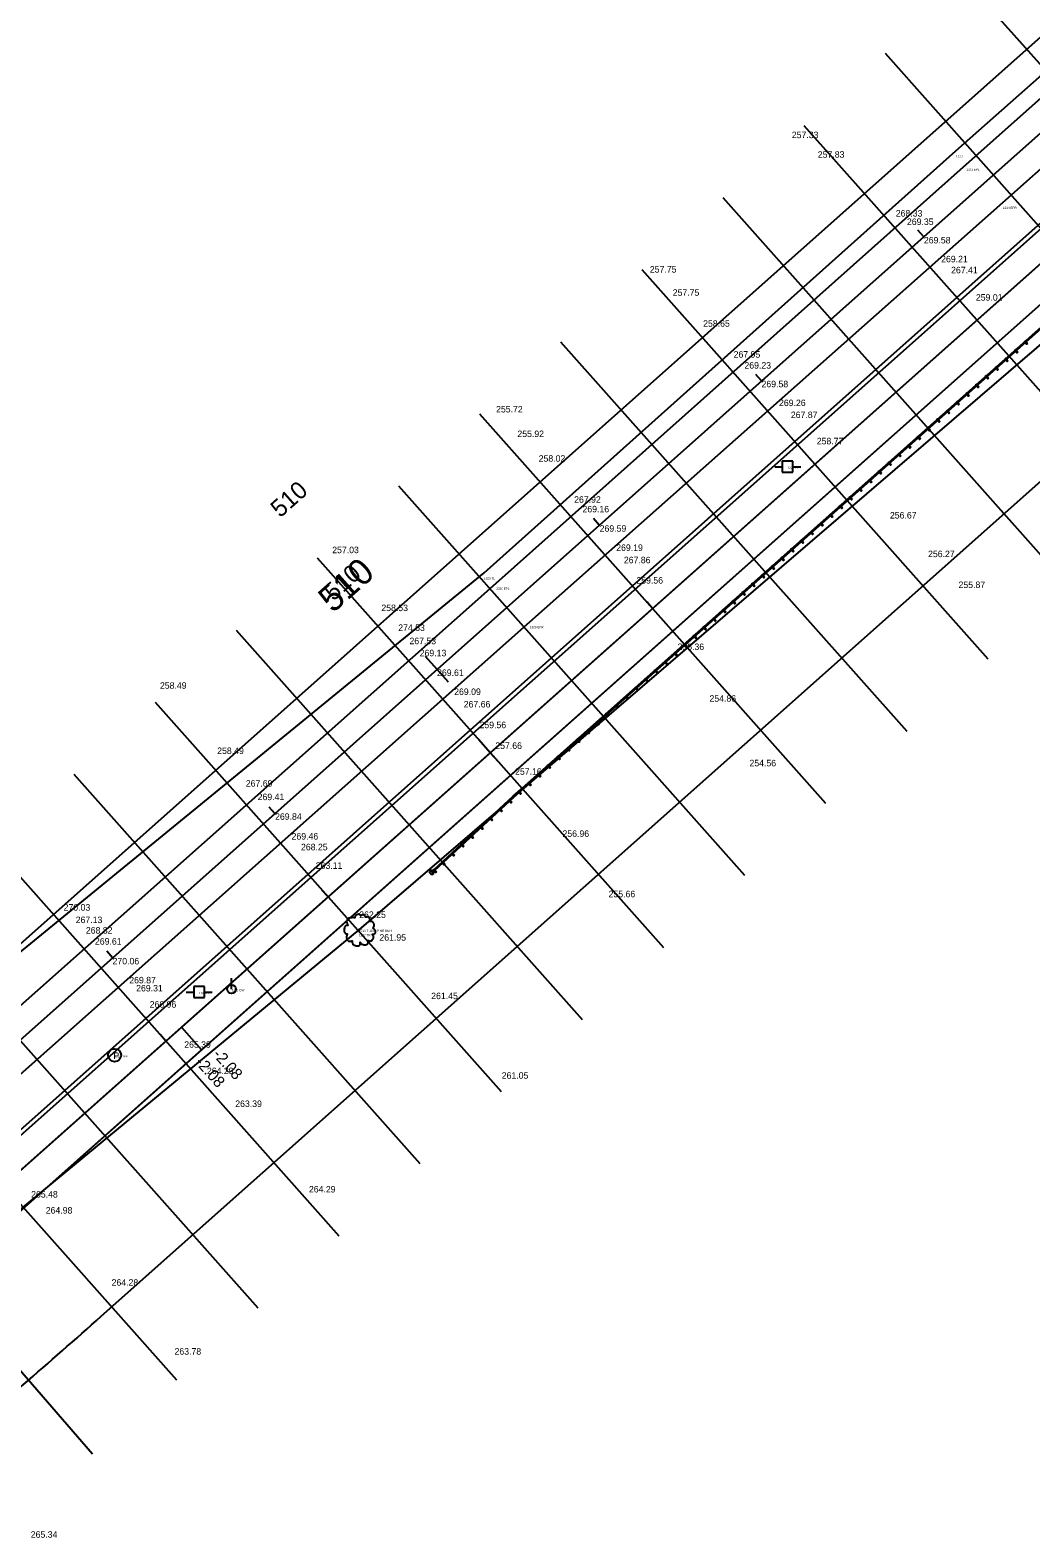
# Model space of a CAD drawing. Extents: x 49683 to 58852, y 49525 to 54803.
# Drawn here: x 52731 to 53192, y 50615 to 51310 of the extents above; entities that cross this region are included whole.
import ezdxf

# ---------------------------------------------------------------- set-up
doc = ezdxf.new("R2010")
doc.units = 0
for name, color, linetype in [('Level 1', 7, 'Continuous'), ('Level 11', 7, 'Continuous'), ('Level 13', 7, 'Continuous'), ('Level 19', 7, 'Continuous'), ('Level 20', 7, 'Continuous'), ('Level 21', 7, 'Continuous'), ('Level 27', 7, 'Continuous'), ('Level 29', 7, 'Continuous'), ('Level 3', 7, 'Continuous'), ('Level 32', 7, 'Continuous'), ('Level 33', 7, 'Continuous'), ('Level 50', 7, 'Continuous'), ('Level 53', 7, 'Continuous'), ('Level 59', 7, 'Continuous'), ('Level 61', 7, 'Continuous'), ('Level 63', 7, 'Continuous'), ('Level 9', 7, 'Continuous')]:
    doc.layers.add(name, color=color, linetype=linetype)

# ---------------------------------------------------------------- blocks, each defined once
blk = doc.blocks.new('TPP')
at = {"layer": 'Level 9'}
blk.add_circle((0, 0), 3, dxfattribs=at)
blk.add_text('P', height=3, dxfattribs=at).set_placement((-0.59, -1.73))
blk = doc.blocks.new('PP')
at = {"layer": 'Level 9'}
for p, q in [((2.53, 2.45), (-2.47, 2.45)), ((-2.47, 2.45), (-2.47, -2.55)), ((2.53, -2.55), (2.53, 2.45)), ((-5.91, -0.11), (-2.44, -0.11)), ((-2.47, -2.55), (2.53, -2.55)), ((2.45, -0.11), (6.09, -0.11))]:
    blk.add_line(p, q, dxfattribs=at)
blk = doc.blocks.new('GW')
at = {"layer": 'Level 9'}
blk.add_line((0, 0), (0, 5), dxfattribs=at)
blk.add_circle((0, 0), 2, dxfattribs=at)
blk = doc.blocks.new('T1')
at = {"layer": 'Level 11'}
for centre, radius in [((0, 0), 0.25), ((-0.01, -0.02), 0.0001)]:
    blk.add_circle(centre, radius, dxfattribs=at)
for points in [[(0.13, 7.17), (-0.17, 7.19), (-0.49, 7.09), (-0.74, 6.99), (-0.97, 6.92), (-1.19, 6.82), (-1.49, 6.64), (-1.72, 6.44), (-1.84, 6.19), (-1.89, 5.97), (-1.94, 5.69), (-1.94, 5.52), (-2.07, 5.49), (-2.22, 5.52), (-2.47, 5.59), (-2.72, 5.59), (-2.97, 5.59), (-3.32, 5.57), (-3.67, 5.57), (-3.94, 5.52), (-4.27, 5.47), (-4.64, 5.34), (-4.99, 5.22), (-5.29, 4.97), (-5.54, 4.49), (-5.67, 4.14), (-5.82, 3.89), (-5.67, 3.44), (-5.49, 3.09), (-5.47, 2.89), (-5.39, 2.47), (-5.29, 2.24), (-5.17, 2.04), (-5.24, 2.02), (-5.62, 1.97), (-5.92, 1.87), (-6.34, 1.64), (-6.57, 1.42), (-6.67, 1.09), (-6.69, 0.75), (-6.79, 0.55), (-6.87, 0.27), (-6.89, 0.2), (-6.94, -0.13), (-6.84, -0.58), (-6.82, -0.93), (-6.69, -1.15), (-6.54, -1.33), (-6.37, -1.58), (-5.97, -1.8), (-5.64, -1.9), (-5.44, -1.93), (-5.62, -2.43), (-5.67, -2.78), (-5.79, -3.18), (-5.79, -3.25), (-5.84, -3.73), (-5.69, -4.05), (-5.62, -4.43), (-5.44, -4.65), (-5.17, -4.95), (-4.84, -5.18), (-4.34, -5.3), (-3.94, -5.28), (-3.37, -5.1), (-3.12, -5.03), (-3.14, -5.2), (-3.12, -5.58), (-3.12, -6), (-2.97, -6.33), (-2.87, -6.6), (-2.72, -6.85), (-2.39, -7.08), (-1.99, -7.15), (-1.57, -7.3), (-1.12, -7.38), (-0.62, -7.4), (-0.02, -7.25), (0.26, -7.13), (0.36, -6.95), (0.56, -6.58), (0.51, -6.35), (0.53, -5.75), (0.63, -5.93), (0.81, -6.28), (1.31, -6.58), (1.71, -6.75), (2.18, -6.9), (2.48, -6.98), (2.96, -6.9), (3.33, -6.83), (3.71, -6.7), (4.01, -6.43), (4.18, -6.15), (4.23, -5.88), (4.31, -5.5), (4.36, -5.33)], [(4.36, -5.33), (4.28, -5.15), (4.23, -4.9), (4.31, -4.93), (4.48, -4.98), (4.75, -5.1), (4.98, -5.18), (5.3, -5.15), (5.58, -5.05), (6.03, -4.78), (6.3, -4.3), (6.58, -3.9), (6.65, -3.58), (6.6, -3.35), (6.58, -2.85), (6.38, -2.6), (6.33, -2.48), (6.23, -2.08), (6.3, -2.03), (6.58, -1.98), (6.95, -1.85), (7.23, -1.73), (7.45, -1.55), (7.53, -1.33), (7.5, -0.93), (7.55, -0.53), (7.48, -0.38), (7.38, -0.23), (7.3, -0.03), (7.15, 0.12), (7.05, 0.27), (6.95, 0.37), (6.83, 0.52), (6.65, 0.65), (6.5, 0.7), (6.45, 0.85), (6.6, 1.04), (6.65, 1.14), (6.68, 1.37), (6.9, 1.72), (6.95, 2.12), (6.9, 2.54), (6.85, 2.82), (6.7, 3.09), (6.5, 3.34), (6.38, 3.52), (6.2, 3.64), (5.88, 3.77), (5.63, 3.82), (5.28, 3.82), (5.08, 3.87), (5.1, 3.92), (5.1, 4.07), (5.1, 4.34), (5.03, 4.79), (4.88, 5.29), (4.88, 5.32), (4.78, 5.57), (4.56, 5.77), (4.38, 5.87), (4.18, 5.99), (3.93, 6.02), (3.63, 6.02), (3.36, 5.97), (3.16, 5.87), (2.98, 5.74), (2.91, 5.89), (2.81, 6.19), (2.76, 6.34), (2.61, 6.52), (2.38, 6.72), (1.93, 6.84), (1.31, 6.77), (1.01, 6.57), (0.86, 6.39), (0.81, 6.52), (0.61, 6.72), (0.51, 6.89), (0.33, 7.02), (0.18, 7.12), (0.08, 7.17)]]:
    blk.add_spline(points, degree=3, dxfattribs=at)

msp = doc.modelspace()

# ---------------------------------------------------------------- linework, layer by layer
at = {"layer": 'Level 1'}
for p, q in [((52544.81, 50683.3), (55534.58, 53340.86)), ((53142.87, 51214.91), (53140.21, 51217.9)), ((53068.13, 51148.47), (53065.47, 51151.46)), ((52993.38, 51082.03), (52990.73, 51085.02)), ((52918.64, 51015.6), (52913.33, 51021.58)), ((52923.96, 51009.62), (52918.64, 51015.6)), ((52843.9, 50949.16), (52841.24, 50952.15)), ((52769.16, 50882.73), (52766.5, 50885.72))]:
    msp.add_line(p, q, dxfattribs=at)
at = {"layer": 'Level 11'}
for p, q in [((53157.7, 51254.45), (53424.49, 51490.93)), ((52940.3, 51059.99), (53157.7, 51254.45)), ((52882.73, 50895.61), (53245.86, 51207.55)), ((52688.43, 50854.08), (52940.3, 51059.99)), ((52579.25, 50645.17), (52882.73, 50895.61))]:
    msp.add_line(p, q, dxfattribs=at)
at = {"layer": 'Level 13'}
for p, q in [((52637.37, 50809.73), (53363.85, 51455.49)), ((53407.7, 51406.16), (52566.74, 50658.64))]:
    msp.add_line(p, q, dxfattribs=at)
at = {"layer": 'Level 19'}
for p, q in [((52714.15, 50773.62), (54181.77, 52078.16)), ((53167.42, 51176.52), (53164.76, 51179.51)), ((53092.67, 51110.08), (53090.02, 51113.07)), ((53017.93, 51043.65), (53015.28, 51046.64)), ((52943.19, 50977.21), (52937.88, 50983.19)), ((52943.19, 50977.21), (52948.51, 50971.23)), ((52868.45, 50910.77), (52865.79, 50913.76)), ((52793.71, 50844.34), (52791.05, 50847.33))]:
    msp.add_line(p, q, dxfattribs=at)
at = {"layer": 'Level 20'}
for p, q in [((52704.85, 50784.08), (53476.26, 51469.77)), ((52723.45, 50763.15), (53495.78, 51449.66))]:
    msp.add_line(p, q, dxfattribs=at)
at = {"layer": 'Level 27'}
for p, q in [((52953.7, 50957.11), (53467.54, 51413.86)), ((52954.03, 50956.74), (53467.88, 51413.49)), ((52953.7, 50957.11), (52916.99, 50923.15)), ((52953.7, 50957.11), (52958.33, 50961.23)), ((52954.04, 50956.75), (52917.33, 50922.78)), ((52915.74, 50923.07), (52914.98, 50922.42)), ((52914.98, 50922.42), (52916.28, 50920.9)), ((52915.74, 50923.07), (52916.99, 50923.15)), ((52915.74, 50923.07), (52917.04, 50921.55)), ((52916.99, 50923.15), (52917.32, 50922.77)), ((52917.32, 50922.77), (52917.04, 50921.55)), ((52917.04, 50921.55), (52916.28, 50920.9))]:
    msp.add_line(p, q, dxfattribs=at)
for points in [[(53190.66, 51165.73), (53190.28, 51165.41), (53189.31, 51166.56), (53189.7, 51166.88)], [(53181.69, 51157.76), (53181.31, 51157.44), (53180.35, 51158.59), (53180.73, 51158.91)], [(53186.18, 51161.74), (53185.79, 51161.42), (53184.83, 51162.57), (53185.21, 51162.89)], [(53177.21, 51153.77), (53176.82, 51153.45), (53175.86, 51154.6), (53176.24, 51154.92)], [(53168.24, 51145.8), (53167.85, 51145.48), (53166.89, 51146.63), (53167.28, 51146.95)], [(53172.72, 51149.78), (53172.34, 51149.46), (53171.38, 51150.62), (53171.76, 51150.94)], [(53159.27, 51137.83), (53158.88, 51137.51), (53157.92, 51138.66), (53158.31, 51138.98)], [(53163.75, 51141.81), (53163.37, 51141.49), (53162.41, 51142.64), (53162.79, 51142.96)], [(53150.3, 51129.85), (53149.92, 51129.53), (53148.95, 51130.68), (53149.34, 51131)], [(53154.78, 51133.84), (53154.4, 51133.52), (53153.44, 51134.67), (53153.82, 51134.99)], [(53145.82, 51125.87), (53145.43, 51125.55), (53144.47, 51126.7), (53144.85, 51127.02)], [(53136.85, 51117.9), (53136.46, 51117.57), (53135.5, 51118.73), (53135.88, 51119.05)], [(53141.33, 51121.88), (53140.95, 51121.56), (53139.99, 51122.71), (53140.37, 51123.03)], [(53127.88, 51109.92), (53127.49, 51109.6), (53126.53, 51110.75), (53126.92, 51111.07)], [(53132.36, 51113.91), (53131.98, 51113.59), (53131.02, 51114.74), (53131.4, 51115.06)], [(53118.91, 51101.95), (53118.52, 51101.63), (53117.56, 51102.78), (53117.95, 51103.1)], [(53123.39, 51105.94), (53123.01, 51105.62), (53122.05, 51106.77), (53122.43, 51107.09)], [(53114.42, 51097.96), (53114.04, 51097.64), (53113.08, 51098.79), (53113.46, 51099.12)], [(53105.45, 51089.99), (53105.07, 51089.67), (53104.11, 51090.82), (53104.49, 51091.14)], [(53109.94, 51093.98), (53109.56, 51093.66), (53108.59, 51094.81), (53108.98, 51095.13)], [(53096.49, 51082.02), (53096.1, 51081.7), (53095.14, 51082.85), (53095.52, 51083.17)], [(53100.97, 51086.01), (53100.59, 51085.69), (53099.62, 51086.84), (53100.01, 51087.16)], [(53087.52, 51074.05), (53087.13, 51073.73), (53086.17, 51074.88), (53086.56, 51075.2)], [(53092, 51078.03), (53091.62, 51077.71), (53090.66, 51078.86), (53091.04, 51079.18)], [(53083.03, 51070.06), (53082.65, 51069.74), (53081.69, 51070.89), (53082.07, 51071.21)], [(53074.06, 51062.09), (53073.68, 51061.77), (53072.72, 51062.92), (53073.1, 51063.24)], [(53078.55, 51066.07), (53078.16, 51065.75), (53077.2, 51066.91), (53077.59, 51067.23)], [(53065.09, 51054.12), (53064.71, 51053.8), (53063.75, 51054.95), (53064.13, 51055.27)], [(53069.58, 51058.1), (53069.2, 51057.78), (53068.23, 51058.93), (53068.62, 51059.25)], [(53060.61, 51050.13), (53060.23, 51049.81), (53059.26, 51050.96), (53059.65, 51051.28)], [(53051.64, 51042.16), (53051.26, 51041.84), (53050.3, 51042.99), (53050.68, 51043.31)], [(53056.13, 51046.14), (53055.74, 51045.82), (53054.78, 51046.97), (53055.16, 51047.3)], [(53042.67, 51034.19), (53042.29, 51033.86), (53041.33, 51035.02), (53041.71, 51035.34)], [(53047.16, 51038.17), (53046.77, 51037.85), (53045.81, 51039), (53046.2, 51039.32)], [(53033.7, 51026.21), (53033.32, 51025.89), (53032.36, 51027.04), (53032.74, 51027.36)], [(53038.19, 51030.2), (53037.8, 51029.88), (53036.84, 51031.03), (53037.23, 51031.35)], [(53029.22, 51022.23), (53028.84, 51021.91), (53027.87, 51023.06), (53028.26, 51023.38)], [(53020.25, 51014.25), (53019.87, 51013.93), (53018.9, 51015.09), (53019.29, 51015.41)], [(53024.73, 51018.24), (53024.35, 51017.92), (53023.39, 51019.07), (53023.77, 51019.39)], [(53011.28, 51006.28), (53010.9, 51005.96), (53009.94, 51007.11), (53010.32, 51007.43)], [(53015.77, 51010.27), (53015.38, 51009.95), (53014.42, 51011.1), (53014.8, 51011.42)], [(53002.31, 50998.31), (53001.93, 50997.99), (53000.97, 50999.14), (53001.35, 50999.46)], [(53006.8, 51002.3), (53006.41, 51001.98), (53005.45, 51003.13), (53005.83, 51003.45)], [(52997.83, 50994.32), (52997.44, 50994), (52996.48, 50995.15), (52996.87, 50995.48)], [(52988.86, 50986.35), (52988.47, 50986.03), (52987.51, 50987.18), (52987.9, 50987.5)], [(52993.34, 50990.34), (52992.96, 50990.02), (52992, 50991.17), (52992.38, 50991.49)], [(52979.89, 50978.38), (52979.51, 50978.06), (52978.54, 50979.21), (52978.93, 50979.53)], [(52984.37, 50982.37), (52983.99, 50982.04), (52983.03, 50983.2), (52983.41, 50983.52)], [(52970.92, 50970.41), (52970.54, 50970.09), (52969.58, 50971.24), (52969.96, 50971.56)], [(52975.41, 50974.39), (52975.02, 50974.07), (52974.06, 50975.22), (52974.44, 50975.54)], [(52966.44, 50966.42), (52966.05, 50966.1), (52965.09, 50967.25), (52965.47, 50967.57)], [(52957.47, 50958.45), (52957.08, 50958.13), (52956.12, 50959.28), (52956.51, 50959.6)], [(52961.95, 50962.43), (52961.57, 50962.11), (52960.61, 50963.27), (52960.99, 50963.59)], [(52948.65, 50950.39), (52948.28, 50950.06), (52947.27, 50951.17), (52947.64, 50951.51)], [(52953.05, 50954.47), (52952.68, 50954.14), (52951.68, 50955.25), (52952.05, 50955.58)], [(52939.84, 50942.24), (52939.47, 50941.91), (52938.46, 50943.02), (52938.83, 50943.36)], [(52944.24, 50946.32), (52943.87, 50945.98), (52942.87, 50947.1), (52943.24, 50947.43)], [(52935.43, 50938.17), (52935.06, 50937.83), (52934.06, 50938.94), (52934.43, 50939.28)], [(52926.63, 50930.02), (52926.25, 50929.68), (52925.25, 50930.79), (52925.62, 50931.13)], [(52931.03, 50934.09), (52930.66, 50933.76), (52929.65, 50934.87), (52930.02, 50935.2)], [(52918.37, 50922.37), (52918, 50922.04), (52916.99, 50923.15), (52917.36, 50923.48)], [(52922.22, 50925.94), (52921.85, 50925.6), (52920.84, 50926.72), (52921.21, 50927.05)]]:
    msp.add_lwpolyline(points, close=True, dxfattribs=at)
at = {"layer": 'Level 29'}
for p, q in [((52714.15, 50773.62), (54181.77, 52078.16)), ((53167.42, 51176.52), (53164.76, 51179.51)), ((53092.67, 51110.08), (53090.02, 51113.07)), ((53017.93, 51043.65), (53015.28, 51046.64)), ((52943.19, 50977.21), (52937.88, 50983.19)), ((52868.45, 50910.77), (52865.79, 50913.76)), ((52793.71, 50844.34), (52791.05, 50847.33))]:
    msp.add_line(p, q, dxfattribs=at)
at = {"layer": 'Level 3'}
for p, q in [((53162.5, 51248.32), (53434.09, 51489.84)), ((53179.35, 51230.72), (53449.72, 51471.81)), ((52945.93, 51055.32), (53162.5, 51248.32)), ((52961.4, 51037.52), (53179.35, 51230.72)), ((52676.2, 50815.96), (52945.93, 51055.32)), ((52668.7, 50777.53), (52961.4, 51037.52))]:
    msp.add_line(p, q, dxfattribs=at)
at = {"layer": 'Level 33'}
msp.add_line((52763.97, 50717.56), (53711.35, 51559.67), dxfattribs=at)
msp.add_arc((50539, 53220.69), 3349.06, 309.99611, 311.63318, dxfattribs=at)
at = {"layer": 'Level 50'}
for p, q in [((53162.43, 51332.65), (53321.88, 51153.27)), ((53125.06, 51299.43), (53284.51, 51120.05)), ((53087.69, 51266.21), (53247.14, 51086.83)), ((53050.32, 51232.99), (53209.77, 51053.61)), ((53012.95, 51199.77), (53172.4, 51020.39)), ((52975.58, 51166.55), (53135.03, 50987.18)), ((52938.21, 51133.34), (53097.66, 50953.96)), ((52900.84, 51100.12), (53060.29, 50920.74)), ((52863.47, 51066.9), (53022.92, 50887.52)), ((52826.1, 51033.68), (52985.55, 50854.3)), ((52788.73, 51000.46), (52948.18, 50821.09)), ((52751.36, 50967.25), (52910.8, 50787.87)), ((52713.99, 50934.03), (52873.43, 50754.65)), ((52676.62, 50900.81), (52836.06, 50721.43)), ((52639.25, 50867.59), (52798.69, 50688.21)), ((52602.88, 50835.64), (52759.93, 50654.16))]:
    msp.add_line(p, q, dxfattribs=at)
at = {"layer": 'Level 63'}
for p, q in [((52716.81, 50794.72), (53451.1, 51447.41)), ((53460.4, 51436.95), (52726.11, 50784.25)), ((53460.4, 51436.95), (52800.86, 50850.69)), ((52810.16, 50840.23), (53469.7, 51426.49)), ((52714.15, 50773.62), (52800.86, 50850.69)), ((52800.86, 50850.69), (52810.16, 50840.23)), ((52800.86, 50850.69), (52810.16, 50840.23)), ((52810.16, 50840.23), (52723.45, 50763.15))]:
    msp.add_line(p, q, dxfattribs=at)

# ---------------------------------------------------------------- block references
at = {"layer": 'Level 11'}
msp.add_blockref('T1', (52882.73, 50895.61), dxfattribs=at)
at = {"layer": 'Level 9'}
for name, p in [('PP', (53080.11, 51109.02)), ('PP', (52809, 50866.96)), ('GW', (52824.02, 50868.26)), ('TPP', (52770.13, 50837.82))]:
    msp.add_blockref(name, p, dxfattribs=at)

# ---------------------------------------------------------------- texts
at = {"layer": 'Level 19'}
msp.add_text('510', height=8, rotation=41.63336, dxfattribs=at).set_placement((52870.93, 51046.77))
at = {"layer": 'Level 21'}
for height, rotation, p in [(8, 41.63333, (52846.38, 51085.16)), (12, 41.63336, (52870.67, 51041.19))]:
    msp.add_text('510', height=height, rotation=rotation, dxfattribs=at).set_placement(p)
at = {"layer": 'Level 32'}
for s, p in [('257.33', (53082.09, 51260.33)), ('257.83', (53094.07, 51251.3)), ('268.33', (53130, 51224.2)), ('269.35', (53135.14, 51220.32)), ('269.58', (53142.94, 51211.82)), ('257.75', (53016.69, 51198.37)), ('269.21', (53150.89, 51203.11)), ('267.41', (53155.48, 51198.05)), ('257.75', (53027.22, 51187.69)), ('259.01', (53166.9, 51185.46)), ('258.65', (53041.25, 51173.44)), ('267.95', (53055.29, 51159.19)), ('269.23', (53060.26, 51154.15)), ('269.58', (53068.14, 51145.55)), ('269.26', (53076.2, 51136.88)), ('255.72', (52945.85, 51133.95)), ('267.87', (53081.65, 51131.36)), ('255.92', (52955.66, 51122.61)), ('258.77', (53093.59, 51119.26)), ('258.02', (52965.47, 51111.26)), ('267.92', (52981.82, 51092.35)), ('269.16', (52985.65, 51087.92)), ('256.67', (53127.3, 51085.08)), ('269.59', (52993.56, 51079)), ('257.03', (52870.36, 51069.12)), ('269.19', (53001.2, 51070.15)), ('256.27', (53144.86, 51067.29)), ('267.86', (53004.72, 51064.47)), ('259.56', (53010.5, 51055.11)), ('255.87', (53158.9, 51053.05)), ('258.53', (52893, 51042.43)), ('274.53', (52900.77, 51033.28)), ('267.53', (52905.94, 51027.18)), ('255.36', (53029.44, 51024.49)), ('269.13', (52910.66, 51021.62)), ('269.61', (52918.66, 51012.56)), ('258.49', (52790.99, 51006.65)), ('269.09', (52926.55, 51003.78)), ('267.66', (52930.94, 50998.03)), ('254.86', (53044.17, 51000.68)), ('259.56', (52938.22, 50988.49)), ('258.49', (52817.37, 50976.58)), ('257.66', (52945.5, 50978.95)), ('254.56', (53062.58, 50970.91)), ('267.69', (52830.55, 50961.54)), ('257.16', (52954.6, 50967.03)), ('269.41', (52836, 50955.33)), ('269.84', (52844.03, 50946.28)), ('269.46', (52851.64, 50937.16)), ('256.96', (52976.44, 50938.41)), ('268.25', (52855.98, 50932.23)), ('263.11', (52862.77, 50923.68)), ('255.66', (52997.68, 50910.59)), ('270.03', (52746.62, 50904.42)), ('267.13', (52752.19, 50898.68)), ('262.25', (52882.8, 50901.07)), ('268.82', (52756.87, 50893.86)), ('269.61', (52761.05, 50888.76)), ('261.95', (52892.09, 50890.59)), ('270.06', (52769.16, 50879.66)), ('269.87', (52776.86, 50870.91)), ('269.31', (52780.03, 50867.2)), ('266.96', (52786.26, 50859.74)), ('261.45', (52915.96, 50863.65)), ('265.39', (52802.19, 50841.24)), ('264.29', (52812.64, 50829.12)), ('261.05', (52948.46, 50826.98)), ('263.39', (52825.69, 50813.97)), ('264.29', (52859.63, 50774.58)), ('265.48', (52731.65, 50772.24)), ('264.98', (52738.39, 50764.86)), ('264.28', (52768.72, 50731.62)), ('263.78', (52797.71, 50699.86)), ('265.34', (52731.48, 50615.51))]:
    msp.add_text(s, height=3, dxfattribs=at).set_placement(p)
at = {"layer": 'Level 53'}
for s, p in [('1331 EPL', (53162.5, 51245.32)), ('1334 EPR', (53179.35, 51227.72)), ('1330 EPL', (52945.93, 51052.32)), ('1329 EPR', (52961.4, 51034.52))]:
    msp.add_text(s, height=1, dxfattribs=at).set_placement(p)
at = {"layer": 'Level 59'}
for s, p in [('1332 PP', (53080.11, 51108.02)), ('1325 PP', (52809, 50865.96)), ('1326 GW', (52824.02, 50867.26)), ('1324 TPP', (52770.13, 50836.82))]:
    msp.add_text(s, height=1, dxfattribs=at).set_placement(p)
at = {"layer": 'Level 61'}
for s, p in [('1333 TL', (53157.7, 51251.45)), ('1328 TL', (52940.3, 51056.99)), ('1710 T 10 IN PINE BM 4', (52882.73, 50894.61)), ('1327 TR', (52882.73, 50892.62))]:
    msp.add_text(s, height=1, dxfattribs=at).set_placement(p)
at = {"layer": 'Level 63'}
for p in [(52815.02, 50837.97), (52806.89, 50834.39)]:
    msp.add_text('-2.08', height=5.25, rotation=311.6332, dxfattribs=at).set_placement(p)

doc.saveas('drawing.dxf')
